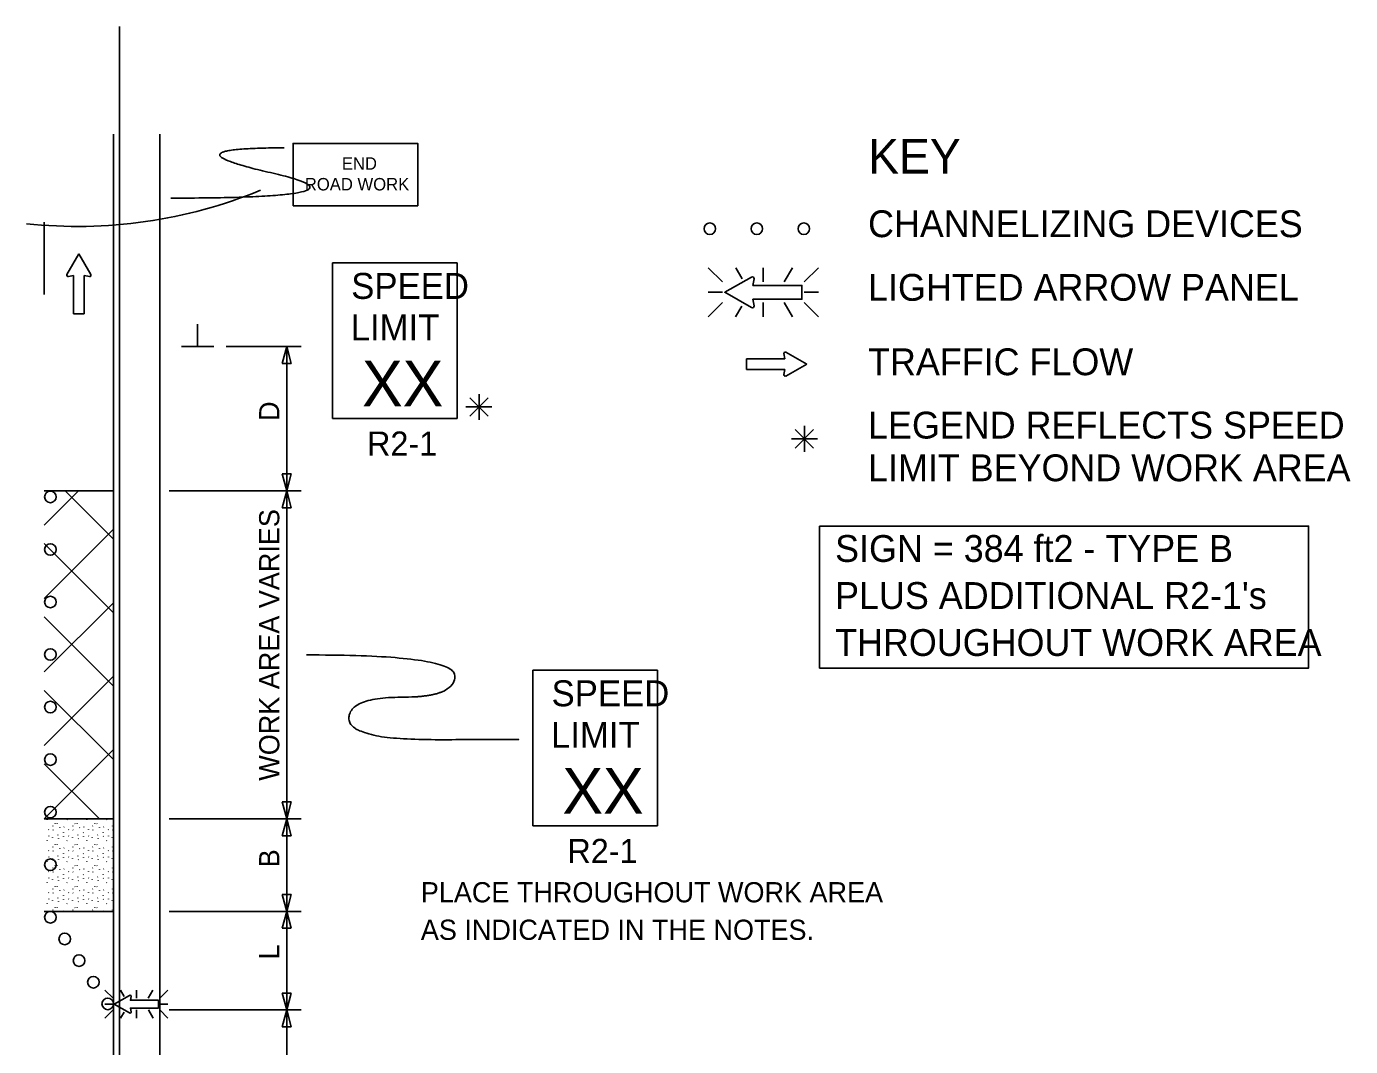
# Model space of a CAD drawing. Extents: x 16737 to 18479, y 5932 to 6964.
# Drawn here: x 16970.5 to 17429.4, y 6610.5 to 6964.1 of the extents above; entities that cross this region are included whole.
import ezdxf

# ---------------------------------------------------------------- set-up
doc = ezdxf.new("R2010")
doc.units = 0
for name, color, linetype in [('ALI_LEGAL_EX', 7, 'Continuous'), ('MT_SCRATCH_LEVEL_E', 7, 'Continuous'), ('PAVT_EDGE_EX', 7, 'Continuous'), ('TRAFFIC_SIGNS_PR', 7, 'Continuous'), ('TYPICAL_TEXT_DIMEN_EX', 7, 'Continuous'), ('TYPICAL_TEXT_DIMEN_PR', 7, 'Continuous')]:
    doc.layers.add(name, color=color, linetype=linetype)

msp = doc.modelspace()

# ---------------------------------------------------------------- linework, layer by layer
at = {"layer": 'ALI_LEGAL_EX'}
msp.add_line((17002.72, 6964.07), (17002.72, 6147.1), dxfattribs=at)
msp.add_lwpolyline([(16976.72, 6896.22), (16976.72, 6871.22)], dxfattribs=at)
at = {"layer": 'MT_SCRATCH_LEVEL_E'}
for p, q in [((16988.68, 6885.31), (16984.56, 6878.07)), ((16992.82, 6878.07), (16988.68, 6885.31)), ((16985.05, 6877.38), (16986.82, 6877.7)), ((16986.82, 6877.7), (16986.82, 6864.44)), ((16990.57, 6864.44), (16990.57, 6877.7)), ((16990.57, 6877.7), (16992.34, 6877.38)), ((16986.82, 6864.44), (16990.57, 6864.44)), ((17240.98, 6847.05), (17233.74, 6851.16)), ((17233.37, 6848.9), (17220.11, 6848.9)), ((17220.11, 6848.9), (17220.11, 6845.16)), ((17233.05, 6850.68), (17233.37, 6848.9)), ((17233.74, 6842.91), (17240.98, 6847.05)), ((17220.11, 6845.16), (17233.37, 6845.16)), ((17233.37, 6845.16), (17233.05, 6843.39))]:
    msp.add_line(p, q, dxfattribs=at)
for centre, start, end in [((16984.97, 6877.84), 150.4248, 279.9638), ((16992.41, 6877.84), 260.0362, 29.7731), ((17233.51, 6850.76), 60.4248, 189.9638), ((17233.51, 6843.32), 170.0362, 299.7731)]:
    msp.add_arc(centre, 0.463, start, end, dxfattribs=at)
at = {"layer": 'PAVT_EDGE_EX'}
for p, q in [((17000.72, 6926.76), (17000.72, 6164.15)), ((17016.72, 6926.76), (17016.72, 6164.15)), ((17000.72, 6803.12), (16976.72, 6803.12)), ((16976.72, 6803.12), (17000.72, 6803.12)), ((16976.72, 6791.22), (16988.62, 6803.12)), ((17000.72, 6786.31), (16983.91, 6803.12)), ((17000.72, 6689.4), (17000.72, 6803.12)), ((16976.72, 6765.77), (17000.72, 6789.77)), ((17000.72, 6760.86), (16976.72, 6784.86)), ((16976.72, 6740.31), (17000.72, 6764.31)), ((17000.72, 6735.4), (16976.72, 6759.4)), ((16976.72, 6714.86), (17000.72, 6738.86)), ((17000.72, 6709.95), (16976.72, 6733.95)), ((16976.72, 6689.4), (17000.72, 6713.4)), ((16995.81, 6689.4), (16976.72, 6708.49)), ((16976.72, 6689.4), (17000.72, 6689.4)), ((16976.72, 6689.4), (17000.72, 6689.4)), ((17000.72, 6689.4), (16976.72, 6689.4)), ((16976.72, 6689.4), (16976.72, 6689.4)), ((16977.65, 6689.04), (16977.7, 6689.16)), ((16978.22, 6685.72), (16978.27, 6685.64)), ((16979.67, 6686.84), (16979.72, 6686.96)), ((16979.75, 6685.58), (16979.8, 6685.5)), ((16980.43, 6687.8), (16980.48, 6687.73)), ((16981.17, 6687.78), (16981.22, 6687.7)), ((16982.04, 6686.4), (16982.09, 6686.32)), ((16983.49, 6686.55), (16983.54, 6686.66)), ((16984.53, 6689.04), (16984.59, 6689.16)), ((16985.1, 6685.72), (16985.16, 6685.64)), ((16986.56, 6686.84), (16986.61, 6686.96)), ((16986.64, 6685.58), (16986.69, 6685.5)), ((16987.32, 6687.8), (16987.37, 6687.73)), ((16988.06, 6687.78), (16988.11, 6687.7)), ((16988.92, 6686.4), (16988.98, 6686.32)), ((16990.37, 6686.55), (16990.42, 6686.66)), ((16991.42, 6689.04), (16991.47, 6689.16)), ((16991.99, 6685.72), (16992.04, 6685.64)), ((16993.44, 6686.84), (16993.49, 6686.96)), ((16993.52, 6685.58), (16993.57, 6685.5)), ((16994.21, 6687.8), (16994.26, 6687.73)), ((16994.94, 6687.78), (16994.99, 6687.7)), ((16995.81, 6686.4), (16995.86, 6686.32)), ((16997.26, 6686.55), (16997.31, 6686.66)), ((16998.31, 6689.04), (16998.36, 6689.16)), ((16998.88, 6685.72), (16998.93, 6685.64)), ((17000.33, 6686.84), (17000.38, 6686.96)), ((17000.41, 6685.58), (17000.46, 6685.5)), ((17000.72, 6657.34), (17000.72, 6689.4)), ((16977.65, 6681.76), (16977.7, 6681.87)), ((16978.27, 6683.51), (16978.32, 6683.43)), ((16979.55, 6682.93), (16979.56, 6682.82)), ((16981.39, 6683.79), (16981.44, 6683.9)), ((16981.58, 6682.59), (16981.63, 6682.51)), ((16983.31, 6684.66), (16983.37, 6684.58)), ((16983.36, 6683.26), (16983.41, 6683.37)), ((16984.53, 6681.76), (16984.59, 6681.87)), ((16985.15, 6683.51), (16985.21, 6683.43)), ((16986.44, 6682.93), (16986.45, 6682.82)), ((16988.28, 6683.79), (16988.33, 6683.9)), ((16988.47, 6682.59), (16988.52, 6682.51)), ((16990.2, 6684.66), (16990.25, 6684.58)), ((16990.24, 6683.26), (16990.3, 6683.37)), ((16991.42, 6681.76), (16991.47, 6681.87)), ((16992.04, 6683.51), (16992.09, 6683.43)), ((16993.32, 6682.93), (16993.33, 6682.82)), ((16995.16, 6683.79), (16995.22, 6683.9)), ((16995.35, 6682.59), (16995.4, 6682.51)), ((16997.09, 6684.66), (16997.14, 6684.58)), ((16997.13, 6683.26), (16997.18, 6683.37)), ((16998.31, 6681.76), (16998.36, 6681.87)), ((16998.93, 6683.51), (16998.98, 6683.43)), ((17000.21, 6682.93), (17000.22, 6682.82)), ((16978.22, 6678.43), (16978.27, 6678.36)), ((16979.67, 6679.56), (16979.72, 6679.68)), ((16979.75, 6678.29), (16979.8, 6678.22)), ((16980.43, 6680.52), (16980.48, 6680.44)), ((16981.17, 6680.49), (16981.22, 6680.41)), ((16981.39, 6676.5), (16981.44, 6676.62)), ((16982.04, 6679.11), (16982.09, 6679.03)), ((16983.31, 6677.37), (16983.37, 6677.3)), ((16983.49, 6679.26), (16983.54, 6679.38)), ((16985.1, 6678.43), (16985.16, 6678.36)), ((16986.56, 6679.56), (16986.61, 6679.68)), ((16986.64, 6678.29), (16986.69, 6678.22)), ((16987.32, 6680.52), (16987.37, 6680.44)), ((16988.06, 6680.49), (16988.11, 6680.41)), ((16988.28, 6676.5), (16988.33, 6676.62)), ((16988.92, 6679.11), (16988.98, 6679.03)), ((16990.2, 6677.37), (16990.25, 6677.3)), ((16990.37, 6679.26), (16990.42, 6679.38)), ((16991.99, 6678.43), (16992.04, 6678.36)), ((16993.44, 6679.56), (16993.49, 6679.68)), ((16993.52, 6678.29), (16993.57, 6678.22)), ((16994.21, 6680.52), (16994.26, 6680.44)), ((16994.94, 6680.49), (16994.99, 6680.41)), ((16995.16, 6676.5), (16995.22, 6676.62)), ((16995.81, 6679.11), (16995.86, 6679.03)), ((16997.09, 6677.37), (16997.14, 6677.3)), ((16997.26, 6679.26), (16997.31, 6679.38)), ((16998.88, 6678.43), (16998.93, 6678.36)), ((17000.33, 6679.56), (17000.38, 6679.68)), ((17000.41, 6678.29), (17000.46, 6678.22)), ((16977.65, 6674.47), (16977.7, 6674.59)), ((16978.27, 6676.22), (16978.32, 6676.15)), ((16979.55, 6675.65), (16979.56, 6675.53)), ((16979.67, 6672.28), (16979.72, 6672.39)), ((16980.43, 6673.23), (16980.48, 6673.16)), ((16981.17, 6673.2), (16981.22, 6673.13)), ((16981.58, 6675.31), (16981.63, 6675.23)), ((16982.04, 6671.83), (16982.09, 6671.75)), ((16983.36, 6675.97), (16983.41, 6676.09)), ((16983.49, 6671.98), (16983.54, 6672.09)), ((16984.53, 6674.47), (16984.59, 6674.59)), ((16985.15, 6676.22), (16985.21, 6676.15)), ((16986.44, 6675.65), (16986.45, 6675.53)), ((16986.56, 6672.28), (16986.61, 6672.39)), ((16987.32, 6673.23), (16987.37, 6673.16)), ((16988.06, 6673.2), (16988.11, 6673.13)), ((16988.47, 6675.31), (16988.52, 6675.23)), ((16988.92, 6671.83), (16988.98, 6671.75)), ((16990.24, 6675.97), (16990.3, 6676.09)), ((16990.37, 6671.98), (16990.42, 6672.09)), ((16991.42, 6674.47), (16991.47, 6674.59)), ((16992.04, 6676.22), (16992.09, 6676.15)), ((16993.32, 6675.65), (16993.33, 6675.53)), ((16993.44, 6672.28), (16993.49, 6672.39)), ((16994.21, 6673.23), (16994.26, 6673.16)), ((16994.94, 6673.2), (16994.99, 6673.13)), ((16995.35, 6675.31), (16995.4, 6675.23)), ((16995.81, 6671.83), (16995.86, 6671.75)), ((16997.13, 6675.97), (16997.18, 6676.09)), ((16997.26, 6671.98), (16997.31, 6672.09)), ((16998.31, 6674.47), (16998.36, 6674.59)), ((16998.93, 6676.22), (16998.98, 6676.15)), ((17000.21, 6675.65), (17000.22, 6675.53)), ((17000.33, 6672.28), (17000.38, 6672.39)), ((16977.65, 6667.19), (16977.7, 6667.3)), ((16978.22, 6671.15), (16978.27, 6671.07)), ((16978.27, 6668.94), (16978.32, 6668.86)), ((16979.55, 6668.36), (16979.56, 6668.25)), ((16979.75, 6671.01), (16979.8, 6670.93)), ((16981.39, 6669.22), (16981.44, 6669.34)), ((16981.58, 6668.02), (16981.63, 6667.94)), ((16983.31, 6670.09), (16983.37, 6670.01)), ((16983.36, 6668.69), (16983.41, 6668.81)), ((16984.53, 6667.19), (16984.59, 6667.3)), ((16985.1, 6671.15), (16985.16, 6671.07)), ((16985.15, 6668.94), (16985.21, 6668.86)), ((16986.44, 6668.36), (16986.45, 6668.25)), ((16986.64, 6671.01), (16986.69, 6670.93)), ((16988.28, 6669.22), (16988.33, 6669.34)), ((16988.47, 6668.02), (16988.52, 6667.94)), ((16990.2, 6670.09), (16990.25, 6670.01)), ((16990.24, 6668.69), (16990.3, 6668.81)), ((16991.42, 6667.19), (16991.47, 6667.3)), ((16991.99, 6671.15), (16992.04, 6671.07)), ((16992.04, 6668.94), (16992.09, 6668.86)), ((16993.32, 6668.36), (16993.33, 6668.25)), ((16993.52, 6671.01), (16993.57, 6670.93)), ((16995.16, 6669.22), (16995.22, 6669.34)), ((16995.35, 6668.02), (16995.4, 6667.94)), ((16997.09, 6670.09), (16997.14, 6670.01)), ((16997.13, 6668.69), (16997.18, 6668.81)), ((16998.31, 6667.19), (16998.36, 6667.3)), ((16998.88, 6671.15), (16998.93, 6671.07)), ((16998.93, 6668.94), (16998.98, 6668.86)), ((17000.21, 6668.36), (17000.22, 6668.25)), ((17000.41, 6671.01), (17000.46, 6670.93)), ((16978.22, 6663.86), (16978.27, 6663.79)), ((16979.67, 6664.99), (16979.72, 6665.11)), ((16979.75, 6663.72), (16979.8, 6663.65)), ((16980.43, 6665.95), (16980.48, 6665.87)), ((16981.17, 6665.92), (16981.22, 6665.84)), ((16982.04, 6664.54), (16982.09, 6664.46)), ((16983.31, 6662.8), (16983.37, 6662.73)), ((16983.49, 6664.69), (16983.54, 6664.81)), ((16985.1, 6663.86), (16985.16, 6663.79)), ((16986.56, 6664.99), (16986.61, 6665.11)), ((16986.64, 6663.72), (16986.69, 6663.65)), ((16987.32, 6665.95), (16987.37, 6665.87)), ((16988.06, 6665.92), (16988.11, 6665.84)), ((16988.92, 6664.54), (16988.98, 6664.46)), ((16990.2, 6662.8), (16990.25, 6662.73)), ((16990.37, 6664.69), (16990.42, 6664.81)), ((16991.99, 6663.86), (16992.04, 6663.79)), ((16993.44, 6664.99), (16993.49, 6665.11)), ((16993.52, 6663.72), (16993.57, 6663.65)), ((16994.21, 6665.95), (16994.26, 6665.87)), ((16994.94, 6665.92), (16994.99, 6665.84)), ((16995.81, 6664.54), (16995.86, 6664.46)), ((16997.09, 6662.8), (16997.14, 6662.73)), ((16997.26, 6664.69), (16997.31, 6664.81)), ((16998.88, 6663.86), (16998.93, 6663.79)), ((17000.33, 6664.99), (17000.38, 6665.11)), ((17000.41, 6663.72), (17000.46, 6663.65)), ((16977.65, 6659.9), (16977.7, 6660.02)), ((16978.27, 6661.65), (16978.32, 6661.58)), ((16979.55, 6661.08), (16979.56, 6660.96)), ((16980.43, 6658.66), (16980.48, 6658.59)), ((16981.17, 6658.64), (16981.22, 6658.56)), ((16981.39, 6661.93), (16981.44, 6662.05)), ((16981.58, 6660.74), (16981.63, 6660.66)), ((16983.36, 6661.4), (16983.41, 6661.52)), ((16984.53, 6659.9), (16984.59, 6660.02)), ((16985.15, 6661.65), (16985.21, 6661.58)), ((16986.44, 6661.08), (16986.45, 6660.96)), ((16987.32, 6658.66), (16987.37, 6658.59)), ((16988.06, 6658.64), (16988.11, 6658.56)), ((16988.28, 6661.93), (16988.33, 6662.05)), ((16988.47, 6660.74), (16988.52, 6660.66)), ((16990.24, 6661.4), (16990.3, 6661.52)), ((16991.42, 6659.9), (16991.47, 6660.02)), ((16992.04, 6661.65), (16992.09, 6661.58)), ((16993.32, 6661.08), (16993.33, 6660.96)), ((16994.21, 6658.66), (16994.26, 6658.59)), ((16994.94, 6658.64), (16994.99, 6658.56)), ((16995.16, 6661.93), (16995.22, 6662.05)), ((16995.35, 6660.74), (16995.4, 6660.66)), ((16997.13, 6661.4), (16997.18, 6661.52)), ((16998.31, 6659.9), (16998.36, 6660.02)), ((16998.93, 6661.65), (16998.98, 6661.58)), ((17000.21, 6661.08), (17000.22, 6660.96)), ((16976.72, 6657.34), (17000.72, 6657.34)), ((16976.72, 6657.34), (17000.72, 6657.34)), ((16979.67, 6657.7), (16979.72, 6657.82)), ((16983.49, 6657.41), (16983.54, 6657.52)), ((16986.56, 6657.7), (16986.61, 6657.82)), ((16990.37, 6657.41), (16990.42, 6657.52)), ((16993.44, 6657.7), (16993.49, 6657.82)), ((16997.26, 6657.41), (16997.31, 6657.52)), ((17000.33, 6657.7), (17000.38, 6657.82))]:
    msp.add_line(p, q, dxfattribs=at)
at = {"layer": 'TRAFFIC_SIGNS_PR'}
for p, q in [((17076.58, 6882.17), (17119.78, 6882.17)), ((17076.58, 6828.17), (17076.58, 6882.17)), ((17119.78, 6828.17), (17119.78, 6882.17)), ((17206.79, 6880.44), (17211.72, 6875.5)), ((17218.55, 6876.61), (17216.34, 6880.44)), ((17225.87, 6875.5), (17225.87, 6880.44)), ((17233.11, 6875.5), (17235.96, 6880.44)), ((17240.02, 6875.5), (17244.96, 6880.44)), ((17211.72, 6871.95), (17206.79, 6871.95)), ((17240.02, 6871.95), (17244.96, 6871.95)), ((17206.79, 6863.46), (17211.72, 6868.39)), ((17216.3, 6863.46), (17218.41, 6867.12)), ((17225.87, 6868.39), (17225.87, 6863.46)), ((17236, 6863.46), (17233.15, 6868.39)), ((17240.02, 6868.39), (17244.96, 6863.45)), ((17076.58, 6828.17), (17119.78, 6828.17)), ((17146.01, 6740.96), (17189.21, 6740.96)), ((17146.01, 6686.96), (17146.01, 6740.96)), ((17189.21, 6686.96), (17189.21, 6740.96)), ((17146.01, 6686.96), (17189.21, 6686.96)), ((16997.71, 6630.03), (17000.53, 6627.21)), ((17004.43, 6627.85), (17003.17, 6630.03)), ((17008.61, 6627.21), (17008.61, 6630.03)), ((17012.75, 6627.21), (17014.38, 6630.03)), ((17016.7, 6627.21), (17019.52, 6630.03)), ((17000.53, 6625.18), (16997.71, 6625.18)), ((16997.71, 6620.33), (17000.53, 6623.15)), ((17003.15, 6620.33), (17004.35, 6622.42)), ((17008.61, 6623.15), (17008.61, 6620.33)), ((17014.4, 6620.33), (17012.77, 6623.15)), ((17016.7, 6625.18), (17019.52, 6625.18)), ((17016.7, 6623.15), (17019.52, 6620.33))]:
    msp.add_line(p, q, dxfattribs=at)
msp.add_lwpolyline([(17062.94, 6901.91), (17106.14, 6901.91), (17106.14, 6923.51), (17062.94, 6923.51)], close=True, dxfattribs=at)
for points in [[(17221.8, 6877.22), (17212.51, 6871.95), (17221.8, 6866.63)], [(17222.67, 6867.25), (17222.27, 6869.52), (17239.29, 6869.52), (17239.29, 6874.32), (17222.27, 6874.32), (17222.68, 6876.6)], [(17006.29, 6628.2), (17000.98, 6625.18), (17006.29, 6622.14)], [(17006.79, 6622.5), (17006.56, 6623.8), (17016.28, 6623.8), (17016.28, 6626.54), (17006.56, 6626.54), (17006.79, 6627.84)]]:
    msp.add_lwpolyline(points, dxfattribs=at)
for centre in [(17207.35, 6893.98), (17223.65, 6893.98), (17239.95, 6893.98), (16978.82, 6801), (16978.82, 6782.79), (16978.82, 6764.57), (16978.82, 6746.36), (16978.82, 6728.15), (16978.82, 6709.93), (16978.82, 6691.72), (16978.82, 6673.5), (16978.82, 6655.29), (16983.79, 6647.78), (16988.76, 6640.27), (16993.73, 6632.77), (16998.7, 6625.26)]:
    msp.add_circle(centre, 2, dxfattribs=at)
for centre, radius, start, end in [((16988.38, 7060.49), 165.74, 263.8185, 292.4458), ((17222.09, 6876.7), 0.598, 350.7308, 118.8916), ((17222.09, 6867.15), 0.597, 241.4833, 9.9593), ((17006.45, 6627.9), 0.341, 350.7308, 118.8916), ((17006.45, 6622.44), 0.341, 241.4833, 9.9593)]:
    msp.add_arc(centre, radius, start, end, dxfattribs=at)
msp.add_open_spline([(17059.88, 6921.99), (17017.37, 6921.99), (17093.89, 6904.57), (17020.55, 6904.57)], degree=2, dxfattribs=at)
at = {"layer": 'TYPICAL_TEXT_DIMEN_EX'}
msp.add_lwpolyline([(17245.38, 6790.88), (17414.83, 6790.88), (17414.83, 6741.68), (17245.38, 6741.68)], close=True, dxfattribs=at)
at = {"layer": 'TYPICAL_TEXT_DIMEN_PR'}
for p, q in [((17029.85, 6853.12), (17029.85, 6860.91)), ((17035.47, 6853.12), (17024.22, 6853.12)), ((17065.72, 6853.12), (17039.72, 6853.12)), ((17059.15, 6847.26), (17060.72, 6853.12)), ((17060.72, 6853.12), (17062.29, 6847.26)), ((17060.72, 6853.12), (17060.72, 6803.12)), ((17060.72, 6847.26), (17059.15, 6847.26)), ((17062.29, 6847.26), (17060.72, 6847.26)), ((17124.17, 6835.38), (17130.55, 6829.01)), ((17130.55, 6835.38), (17124.17, 6829.01)), ((17127.36, 6832.19), (17127.36, 6836.65)), ((17127.36, 6832.19), (17122.83, 6832.19)), ((17127.36, 6832.19), (17130.55, 6832.19)), ((17127.36, 6832.19), (17131.84, 6832.19)), ((17127.36, 6832.19), (17127.36, 6827.69)), ((17243.33, 6824.33), (17236.95, 6817.95)), ((17236.96, 6824.33), (17243.33, 6817.95)), ((17240.14, 6821.14), (17240.14, 6825.59)), ((17240.14, 6821.14), (17235.61, 6821.14)), ((17240.14, 6821.14), (17243.33, 6821.14)), ((17240.14, 6821.14), (17244.62, 6821.14)), ((17240.14, 6821.14), (17240.14, 6816.64)), ((17060.72, 6803.12), (17059.15, 6808.99)), ((17059.15, 6808.99), (17060.72, 6808.99)), ((17060.72, 6808.99), (17062.29, 6808.99)), ((17062.29, 6808.99), (17060.72, 6803.12)), ((17065.72, 6803.12), (17020.02, 6803.12)), ((17059.15, 6797.26), (17060.72, 6803.12)), ((17060.72, 6689.4), (17060.72, 6803.12)), ((17060.72, 6803.12), (17062.29, 6797.26)), ((17060.72, 6797.26), (17059.15, 6797.26)), ((17062.29, 6797.26), (17060.72, 6797.26)), ((17060.72, 6689.4), (17059.15, 6695.26)), ((17059.15, 6695.26), (17060.72, 6695.26)), ((17060.72, 6695.26), (17062.29, 6695.26)), ((17062.29, 6695.26), (17060.72, 6689.4)), ((17065.72, 6689.4), (17020.02, 6689.4)), ((17059.15, 6683.54), (17060.72, 6689.4)), ((17060.72, 6657.34), (17060.72, 6689.4)), ((17060.72, 6689.4), (17062.29, 6683.54)), ((17060.72, 6683.54), (17059.15, 6683.54)), ((17062.29, 6683.54), (17060.72, 6683.54)), ((17060.72, 6657.34), (17059.15, 6663.2)), ((17059.15, 6663.2), (17060.72, 6663.2)), ((17060.72, 6663.2), (17062.29, 6663.2)), ((17062.29, 6663.2), (17060.72, 6657.34)), ((17065.72, 6657.34), (17020.02, 6657.34)), ((17059.15, 6651.48), (17060.72, 6657.34)), ((17060.72, 6623.15), (17060.72, 6657.34)), ((17060.72, 6657.34), (17062.29, 6651.48)), ((17060.72, 6651.48), (17059.15, 6651.48)), ((17062.29, 6651.48), (17060.72, 6651.48)), ((17060.72, 6623.15), (17059.15, 6629.01)), ((17059.15, 6629.01), (17060.72, 6629.01)), ((17060.72, 6629.01), (17062.29, 6629.01)), ((17062.29, 6629.01), (17060.72, 6623.15)), ((17065.72, 6623.15), (17020.02, 6623.15)), ((17065.72, 6623.15), (17020.02, 6623.15)), ((17059.15, 6617.29), (17060.72, 6623.15)), ((17060.72, 6623.15), (17060.72, 6573.15)), ((17060.72, 6623.15), (17062.29, 6617.29)), ((17060.72, 6617.29), (17059.15, 6617.29)), ((17062.29, 6617.29), (17060.72, 6617.29))]:
    msp.add_line(p, q, dxfattribs=at)
msp.add_open_spline([(17067.58, 6746.26), (17119.03, 6746.26), (17119.03, 6731.56), (17082.28, 6731.56), (17082.28, 6716.86), (17141.08, 6716.86), (17141.08, 6716.86)], degree=2, dxfattribs=at)

# ---------------------------------------------------------------- texts
at = {"layer": 'TRAFFIC_SIGNS_PR'}
for s, height, p in [('END', 4.31, (17079.82, 6914.43)), ('ROAD WORK', 4.31, (17067, 6907.24)), ('SPEED', 9, (17083.07, 6869.64)), ('LIMIT', 9, (17082.89, 6855.24)), ('XX', 15.785, (17086.83, 6832.4)), ('R2-1', 8.37, (17088.59, 6815.3)), ('SPEED', 9, (17152.5, 6728.43)), ('LIMIT', 9, (17152.31, 6714.03)), ('XX', 15.785, (17156.26, 6691.19)), ('R2-1', 8.37, (17158.02, 6674.09)), ('PLACE THROUGHOUT WORK AREA', 7, (17107.2, 6660.46)), ('AS INDICATED IN THE NOTES.', 7, (17107.2, 6647.46))]:
    msp.add_text(s, height=height, dxfattribs=at).set_placement(p)
at = {"layer": 'TYPICAL_TEXT_DIMEN_EX'}
for s, height, p in [('KEY', 12, (17262.19, 6913.09)), ('CHANNELIZING DEVICES', 9.3, (17262.19, 6891.04)), ('LIGHTED ARROW PANEL', 9.3, (17262.19, 6868.99)), ('TRAFFIC FLOW', 9.3, (17262.19, 6843.19)), ('LEGEND REFLECTS SPEED', 9.3, (17262.19, 6821.24)), ('LIMIT BEYOND WORK AREA', 9.3, (17262.19, 6806.44)), ('SIGN = 384 ft2 - TYPE B', 9.3, (17250.77, 6778.47)), ("PLUS ADDITIONAL R2-1's", 9.3, (17250.77, 6762.17)), ('THROUGHOUT WORK AREA', 9.3, (17250.77, 6745.87))]:
    msp.add_text(s, height=height, dxfattribs=at).set_placement(p)
at = {"layer": 'TYPICAL_TEXT_DIMEN_PR'}
for s, p in [('D', (17058.16, 6827.34)), ('WORK AREA VARIES', (17058.16, 6702.62)), ('B', (17058.16, 6672.6)), ('L', (17058.16, 6640.63))]:
    msp.add_text(s, height=7, rotation=90, dxfattribs=at).set_placement(p)

doc.saveas('drawing.dxf')
